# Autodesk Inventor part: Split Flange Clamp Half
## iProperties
Category: Hydraulics
Title: Split Flange Clamp Half
Subject: Hydraulic Adapters
Author: QBZ
Shininess: 41.0
PropertySet Name: _Private Model Information
Created: 2001-03
Part Number: 449-74446-8
Material: Steel, Mild
Catalog Web Link: http://www.aeroquip.com
Document SubType Name: Modeling
Designer: QBZ
Description: Split Flange Clamp -8
Control State: 0
Master: False
Checked Out: False
PropertySet Name: Design Tracking Control
Density: 7.860000000000001
Volumn: 6.946206585211241
Area: 37.36297771493962
PropertySet Name: Model Information
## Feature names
1. Extrusion1
2. Hole1
3. Extrusion3
4. Fillet1
